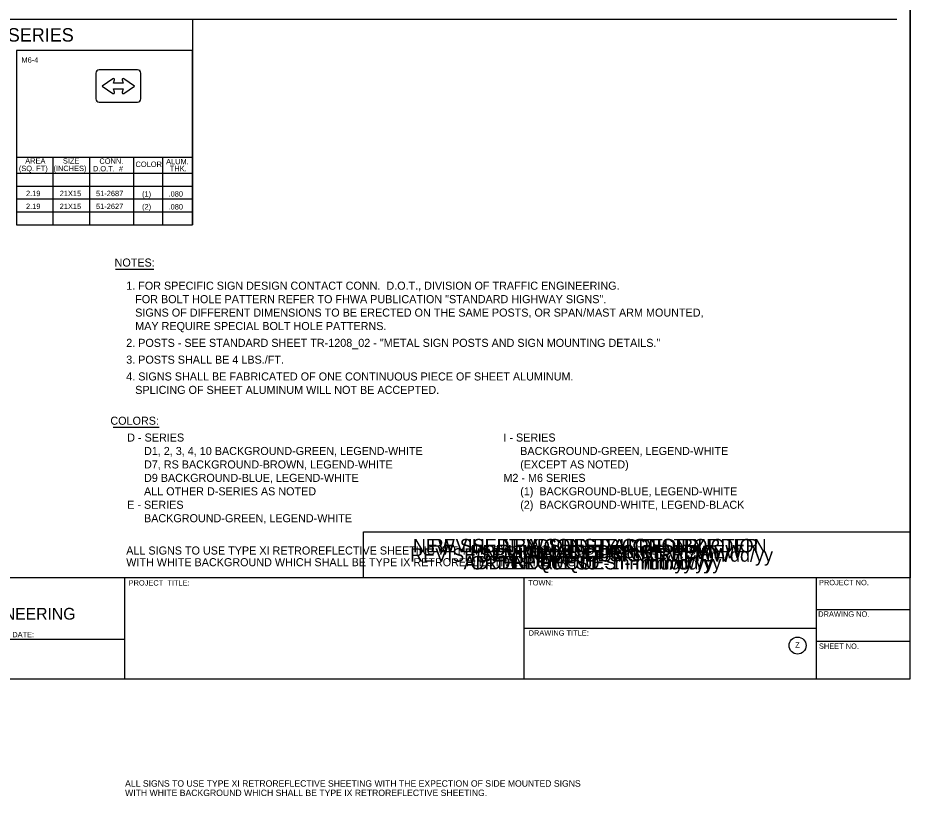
# Model space of a CAD drawing. Extents: x 0 to 2011, y -71 to 1183.
# Drawn here: x 739 to 1270, y -71 to 392 of the extents above; entities that cross this region are included whole.
import ezdxf

# ---------------------------------------------------------------- set-up
doc = ezdxf.new("R2010")
doc.units = 0
for name, color, linetype in [('CT_Bdr_Txt_Titleblock', 7, 'Continuous'), ('CT_Border_Perimeter_Shape', 7, 'Continuous'), ('CT_Construction', 7, 'Continuous'), ('CT_Note_Final_Design_Review', 7, 'Continuous'), ('CT_Note_New_Sheet_by_Addendum', 7, 'Continuous'), ('CT_Note_New_Sheet_by_Const_Order', 7, 'Continuous'), ('CT_Note_Preliminary_Design_Review', 7, 'Continuous'), ('CT_Note_Revised_Sheet_by_Addendum', 7, 'Continuous'), ('CT_Note_Revised_Sheet_by_Const_Order', 7, 'Continuous'), ('CT_Note_Semi_Final_Design_Review', 7, 'Continuous'), ('CT_Signature_Field_CTDOT', 7, 'Continuous'), ('CT_Title_Block_Linework', 7, 'Continuous'), ('CT_Title_Block_Text', 7, 'Continuous'), ('Default', 7, 'Continuous'), ('Level 1', 7, 'Continuous'), ('Level 2', 7, 'Continuous'), ('Level 5', 7, 'Continuous')]:
    doc.layers.add(name, color=color, linetype=linetype)

msp = doc.modelspace()

# ---------------------------------------------------------------- linework, layer by layer
at = {"layer": 'CT_Border_Perimeter_Shape'}
msp.add_lwpolyline([(0, -0.97), (1270, -0.97), (1270, 829.03), (0, 829.03)], close=True, dxfattribs=at)
at = {"layer": 'CT_Construction'}
msp.add_lwpolyline([(0, 829.03), (1270, 829.03), (1270, 59.03), (0, 59.03)], close=True, dxfattribs=at)
at = {"layer": 'CT_Note_Final_Design_Review'}
msp.add_lwpolyline([(944.83, 86.47), (1270, 86.47), (1270, 59.03), (944.83, 59.03)], close=True, dxfattribs=at)
at = {"layer": 'CT_Note_New_Sheet_by_Addendum'}
msp.add_lwpolyline([(944.83, 86.47), (1270, 86.47), (1270, 59.03), (944.83, 59.03)], close=True, dxfattribs=at)
msp.add_lwpolyline([(944.83, 86.47), (1270, 86.47), (1270, 59.03), (944.83, 59.03)], close=True, dxfattribs=at)
at = {"layer": 'CT_Note_New_Sheet_by_Const_Order'}
msp.add_lwpolyline([(944.83, 86.47), (1270, 86.47), (1270, 59.03), (944.83, 59.03)], close=True, dxfattribs=at)
msp.add_lwpolyline([(944.83, 86.47), (1270, 86.47), (1270, 59.03), (944.83, 59.03)], close=True, dxfattribs=at)
at = {"layer": 'CT_Note_Preliminary_Design_Review'}
msp.add_lwpolyline([(944.83, 86.47), (1270, 86.47), (1270, 59.03), (944.83, 59.03)], close=True, dxfattribs=at)
at = {"layer": 'CT_Note_Revised_Sheet_by_Addendum'}
msp.add_lwpolyline([(944.83, 86.47), (1270, 86.47), (1270, 59.03), (944.83, 59.03)], close=True, dxfattribs=at)
msp.add_lwpolyline([(944.83, 86.47), (1270, 86.47), (1270, 59.03), (944.83, 59.03)], close=True, dxfattribs=at)
at = {"layer": 'CT_Note_Revised_Sheet_by_Const_Order'}
msp.add_lwpolyline([(944.83, 86.47), (1270, 86.47), (1270, 59.03), (944.83, 59.03)], close=True, dxfattribs=at)
msp.add_lwpolyline([(944.83, 86.47), (1270, 86.47), (1270, 59.03), (944.83, 59.03)], close=True, dxfattribs=at)
at = {"layer": 'CT_Note_Semi_Final_Design_Review'}
msp.add_lwpolyline([(944.83, 86.47), (1270, 86.47), (1270, 59.03), (944.83, 59.03)], close=True, dxfattribs=at)
msp.add_lwpolyline([(944.83, 86.47), (1270, 86.47), (1270, 59.03), (944.83, 59.03)], close=True, dxfattribs=at)
at = {"layer": 'CT_Signature_Field_CTDOT'}
msp.add_line((651.86, 22.46), (802.52, 22.46), dxfattribs=at)
at = {"layer": 'CT_Title_Block_Linework'}
for p, q in [((1270, 59.03), (0, 59.03)), ((802.52, 59.03), (802.52, -0.97)), ((1040.16, 59.03), (1040.16, -0.97)), ((1214.02, 59.03), (1214.02, -0.97)), ((1214.02, 40.28), (1270, 40.28)), ((1040.16, 29.03), (1214.02, 29.03)), ((1214.02, 21.28), (1270, 21.28))]:
    msp.add_line(p, q, dxfattribs=at)
msp.add_circle((1203.02, 18.75), 5.08, dxfattribs=at)
at = {"layer": 'Default'}
msp.add_line((1262.03, 391.26), (5.05, 391.26), dxfattribs=at)
at = {"layer": 'Level 1'}
for p, q in [((810.43, 361.2), (787.48, 361.2)), ((810.43, 361.2), (787.48, 361.2)), ((785.57, 359.29), (785.57, 343.99)), ((785.57, 359.29), (785.57, 343.99)), ((795.73, 355.99), (789.39, 351.64)), ((808.52, 351.64), (802.18, 355.99)), ((812.34, 343.99), (812.34, 359.29)), ((812.34, 343.99), (812.34, 359.29)), ((789.39, 351.64), (789.39, 351.64)), ((789.39, 351.64), (795.73, 347.29)), ((796.11, 353.32), (796.7, 355.28)), ((801.8, 353.32), (796.11, 353.32)), ((801.21, 355.28), (801.8, 353.32)), ((802.18, 347.29), (808.52, 351.64)), ((808.52, 351.64), (808.52, 351.64)), ((808.52, 351.64), (808.52, 351.64)), ((796.7, 348), (796.11, 349.97)), ((796.11, 349.97), (801.8, 349.97)), ((801.8, 349.97), (801.21, 348)), ((787.48, 342.08), (810.43, 342.08)), ((787.48, 342.08), (810.43, 342.08)), ((797.3, 242.69), (820.15, 242.69)), ((795.89, 148.62), (823.17, 148.62))]:
    msp.add_line(p, q, dxfattribs=at)
for centre, radius, start, end in [((787.48, 359.29), 1.91, 90, 180), ((787.48, 359.29), 1.91, 90, 180), ((810.43, 359.29), 1.91, 0, 90), ((810.43, 359.29), 1.91, 0, 90), ((796.09, 355.47), 0.637, 343.3591, 124.4886), ((801.82, 355.47), 0.637, 55.5114, 196.6409), ((796.09, 347.82), 0.637, 235.5114, 16.6409), ((801.82, 347.82), 0.637, 163.3591, 304.4886), ((787.48, 343.99), 1.91, 180, 270), ((787.48, 343.99), 1.91, 180, 270), ((810.43, 343.99), 1.91, 270, 360), ((810.43, 343.99), 1.91, 270, 360)]:
    msp.add_arc(centre, radius, start, end, dxfattribs=at)
at = {"layer": 'Level 2'}
for p, q in [((812.34, 361.2), (812.34, 361.2)), ((785.57, 342.08), (785.57, 342.08)), ((738.29, 309.4), (843.04, 309.4)), ((760.04, 309.4), (760.04, 269.13)), ((781.79, 309.4), (781.79, 269.13)), ((807.89, 309.4), (807.89, 269.13)), ((825.29, 309.4), (825.29, 269.13)), ((738.29, 299.81), (843.04, 299.81)), ((738.29, 292.14), (843.04, 292.14)), ((738.29, 284.47), (843.04, 284.47)), ((738.29, 276.8), (843.04, 276.8))]:
    msp.add_line(p, q, dxfattribs=at)
msp.add_lwpolyline([(843.04, 372.75), (738.29, 372.75), (738.29, 269.13), (843.04, 269.13)], close=True, dxfattribs=at)
msp.add_lwpolyline([(804.12, 354.65), (804.12, 354.66)], dxfattribs=at)
at = {"layer": 'Level 5'}
msp.add_line((843.04, 391.26), (843.04, 269.13), dxfattribs=at)

# ---------------------------------------------------------------- texts
at = {"layer": 'CT_Bdr_Txt_Titleblock'}
msp.add_text('Z', height=3.2, dxfattribs=at).set_placement((1201.62, 17.47))
at = {"layer": 'CT_Note_Final_Design_Review'}
msp.add_text('FINAL DESIGN REVIEW', height=8, dxfattribs=at).set_placement((1032.99, 70.22))
at = {"layer": 'CT_Note_New_Sheet_by_Addendum'}
for s, p in [('NEW SHEET ADDED BY', (1026.89, 74.2)), ('ADDENDUM NO. 1 - mm/dd/yy', (1004.36, 64.04))]:
    msp.add_text(s, height=8, dxfattribs=at).set_placement(p)
at = {"layer": 'CT_Note_New_Sheet_by_Const_Order'}
for s, p in [('NEW SHEET ADDED BY CONSTRUCTION', (974.21, 74.2)), ('ORDER REQUEST - mm/dd/yy', (1008.44, 64.04))]:
    msp.add_text(s, height=8, dxfattribs=at).set_placement(p)
at = {"layer": 'CT_Note_Preliminary_Design_Review'}
msp.add_text('PRELIMINARY DESIGN REVIEW', height=8, rotation=360, dxfattribs=at).set_placement((1008.39, 70.59))
at = {"layer": 'CT_Note_Revised_Sheet_by_Addendum'}
msp.add_text('REVISED BY ADDENDUM NO. 1 - mm/dd/yy', height=8, dxfattribs=at).set_placement((972.63, 68.66))
at = {"layer": 'CT_Note_Revised_Sheet_by_Const_Order'}
for s, p in [('REVISED BY CONSTRUCTION ORDER', (984.74, 74.19)), ('REQUEST - mm/dd/yy', (1032.95, 64.03))]:
    msp.add_text(s, height=8, dxfattribs=at).set_placement(p)
at = {"layer": 'CT_Note_Semi_Final_Design_Review'}
msp.add_text('SEMI FINAL DESIGN REVIEW', height=8, dxfattribs=at).set_placement((1013.84, 68.77))
at = {"layer": 'CT_Signature_Field_CTDOT'}
for s, height, p in [('OFFICE OF ENGINEERING', 7, (655.38, 34.16)), ('DATE:  ', 3.2, (735.85, 23.69))]:
    msp.add_text(s, height=height, rotation=360, dxfattribs=at).set_placement(p)
at = {"layer": 'CT_Title_Block_Text'}
for s, p in [('PROJECT  TITLE:', (805.05, 54.43)), ('TOWN:', (1042.74, 54.53)), ('PROJECT NO.', (1215.74, 54.64)), ('DRAWING NO.', (1215.31, 35.88)), ('DRAWING TITLE:', (1043.02, 24.66)), ('SHEET NO.', (1215.72, 16.78))]:
    msp.add_text(s, height=3.2, rotation=360, dxfattribs=at).set_placement(p)
at = {"layer": 'Level 1'}
for s, height, p in [('M6 - SERIES', 8, (708.8, 378.08)), ('NOTES:', 4.8, (796.71, 244.23)), ('1. FOR SPECIFIC SIGN DESIGN CONTACT CONN.  D.O.T., DIVISION OF TRAFFIC ENGINEERING.', 4.8, (803.64, 230.46)), ('   FOR BOLT HOLE PATTERN REFER TO FHWA PUBLICATION "STANDARD HIGHWAY SIGNS".', 4.8, (803.64, 222.46)), ('   SIGNS OF DIFFERENT DIMENSIONS TO BE ERECTED ON THE SAME POSTS, OR SPAN/MAST ARM MOUNTED,', 4.8, (803.64, 214.46)), ('   MAY REQUIRE SPECIAL BOLT HOLE PATTERNS.', 4.8, (803.64, 206.46)), ('2. POSTS - SEE STANDARD SHEET TR-1208_02 - "METAL SIGN POSTS AND SIGN MOUNTING DETAILS."', 4.8, (803.64, 196.46)), ('3. POSTS SHALL BE 4 LBS./FT.', 4.8, (803.64, 186.46)), ('4. SIGNS SHALL BE FABRICATED OF ONE CONTINUOUS PIECE OF SHEET ALUMINUM.', 4.8, (803.64, 176.46)), ('   SPLICING OF SHEET ALUMINUM WILL NOT BE ACCEPTED.', 4.8, (803.64, 168.46)), ('COLORS:', 4.8, (794.22, 150.12)), ('D - SERIES', 4.8, (804.22, 140.12)), ('I - SERIES', 4.8, (1028.02, 140.12)), ('D1, 2, 3, 4, 10 BACKGROUND-GREEN, LEGEND-WHITE', 4.8, (814.22, 132.12)), ('BACKGROUND-GREEN, LEGEND-WHITE', 4.8, (1038.02, 132.12)), ('D7, RS BACKGROUND-BROWN, LEGEND-WHITE', 4.8, (814.22, 124.12)), ('(EXCEPT AS NOTED)', 4.8, (1038.02, 124.12)), ('D9 BACKGROUND-BLUE, LEGEND-WHITE', 4.8, (814.22, 116.12)), ('M2 - M6 SERIES', 4.8, (1028.02, 116.12)), ('ALL OTHER D-SERIES AS NOTED', 4.8, (814.22, 108.12)), ('(1)  BACKGROUND-BLUE, LEGEND-WHITE', 4.8, (1038.02, 108.12)), ('E - SERIES', 4.8, (804.22, 100.12)), ('(2)  BACKGROUND-WHITE, LEGEND-BLACK', 4.8, (1038.02, 100.12)), ('BACKGROUND-GREEN, LEGEND-WHITE', 4.8, (814.22, 92.12)), ('ALL SIGNS TO USE TYPE XI RETROREFLECTIVE SHEETING WITH THE EXCEPTION OF SIDE MOUNTED SIGNS ', 4.8, (803.64, 72.9)), ('WITH WHITE BACKGROUND WHICH SHALL BE TYPE IX RETROREFLECTIVE SHEETING.', 4.8, (803.64, 65.94)), ('ALL SIGNS TO USE TYPE XI RETROREFLECTIVE SHEETING WITH THE EXPECTION OF SIDE MOUNTED SIGNS ', 3.84, (802.97, -65.23)), ('WITH WHITE BACKGROUND WHICH SHALL BE TYPE IX RETROREFLECTIVE SHEETING.', 3.84, (802.97, -70.8))]:
    msp.add_text(s, height=height, dxfattribs=at).set_placement(p)
at = {"layer": 'Level 2'}
for s, p in [('M6-4', (741.3, 365.54)), ('AREA', (743.56, 305.52)), ('SIZE', (765.97, 305.52)), ('CONN.', (787.69, 305.37)), ('ALUM.', (827.35, 305.14)), ('(SQ. FT)', (739.77, 301.05)), ('(INCHES)', (760.34, 301.05)), ('D.O.T.  #', (783.82, 300.9)), ('COLOR', (809.16, 303.52)), ('THK.', (829.53, 301))]:
    msp.add_text(s, height=3.2, dxfattribs=at).set_placement(p)
at = {"layer": 'Level 5'}
for s, p in [(' 2.19', (742.79, 286.14)), ('21X15', (764.06, 286.14)), ('51-2687', (785.66, 286.14)), ('(1)', (813.05, 285.87)), ('.080', (828.81, 285.87)), (' 2.19', (742.79, 278.47)), ('21X15', (764.06, 278.47)), ('51-2627', (785.66, 278.47)), ('(2)', (813.05, 278.2)), ('.080', (828.81, 278.2))]:
    msp.add_text(s, height=3.2, dxfattribs=at).set_placement(p)

doc.saveas('drawing.dxf')
